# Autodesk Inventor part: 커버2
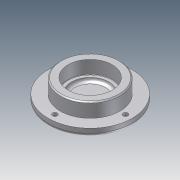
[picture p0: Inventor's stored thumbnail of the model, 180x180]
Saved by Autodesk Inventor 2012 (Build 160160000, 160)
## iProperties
Company: 한국ATC센터
Created: 2014-10
Part Number: 커버2
Document SubType Name: Modeling
Designer: KYOUNG IL JANG
Density: 1 g/cm^3
Mass: 44.7286 g
Surface Area: 161.165 cm^2
Volume: 44.7286 cm^3
Material: 기본값
Author: KYOUNG IL JANG
Revision Number: 1
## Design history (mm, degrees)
sketch "스케치1"
  geometry: C1 r 38 at (0, 0); 1 further point
  constraints: 1 centre point, 1 coincident
  dimensions: "d0" = 76 diameter of C1
extrude "돌출1" new body sketch "스케치1" distance "d1" = 7; taper "d2" = 0 deg
sketch "스케치2"
  geometry: C1 r 27 at (0, 0); 1 further point
  constraints: 1 centre point, 1 coincident
  dimensions: "d3" = 54 diameter of C1
extrude "돌출2" join sketch "스케치2" distance "d4" = 13; taper "d5" = 0 deg
hole "구멍2" diameter "d20" = 34; stored, may be unused: countersink angle "d24" = 90 deg, drill point angle "d26" = 0 deg; dims "d18" = 10, "d19" = 10, "d21" = 6, "d22" = 40, "d23" = 12, "d25" = 3
fillet "모깎기2" dims "d34" = 3
fillet "모깎기1" dims "d27" = 0.3
chamfer "모따기1" distance "d28" = 1; stored, may be unused: second distance "d29" = 2, angle "d30" = 45 deg
sketch "스케치4" dims "d35" = 64
  geometry: 3 further points
  constraints: 2 horizontal alignment, 1 coincident, 2 other
hole "구멍3" sketch "스케치4" at (32, 0) diameter "d36" = 4.5; stored, may be unused: countersink angle "d40" = 90 deg, drill point angle "d42" = 118 deg; dims "d37" = 6, "d38" = 8, "d39" = 4.4, "d41" = 13
node "솔리드1"
pattern_circular "원형 패턴1" dims angle "d44" = 360 deg
